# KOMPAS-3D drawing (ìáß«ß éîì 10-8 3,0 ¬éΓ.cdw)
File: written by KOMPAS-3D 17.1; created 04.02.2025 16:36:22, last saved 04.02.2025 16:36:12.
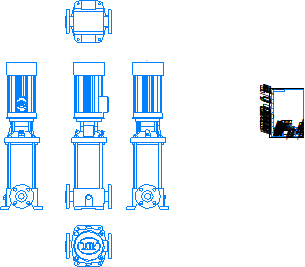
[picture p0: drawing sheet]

Sheet 1: A4, portrait

Title block, sheet 1: name: Насос ВМН 10-8 3,0 / кВт; designation: Насос ВМН 10-8 3,0 кВт; material: Сталь 10  ГОСТ 1050-2013; mass: 164,53; sheets: 1; sheet format: A4; stored path: \\adlc.lan\data\АДЛ_ПКД\3D-модели\ADL production\Насосы ГРАНПАМП\Насосы ВМН\ВМН10\KOMPAS 3D\Насос ВМН 10-8 3,0 кВт.cdw

Views: Вид 1, Спереди, Проекционный вид 2, Проекционный вид 3, Проекционный вид 4, Проекционный вид 5
Referenced files in \\adlc.lan\data\АДЛ_ПКД\3D-модели\ADL production\Насосы ГРАНПАМП\Насосы ВМН\ВМН10\KOMPAS 3D\: ВМН 10-8 3,0 кВт.m3d, Насос ВМН 10-8 3,0 кВт.m3d
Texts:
  Andrey
  АДЛ
Dimensions and other numbers on the sheet: 1:1; 1; 164,53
